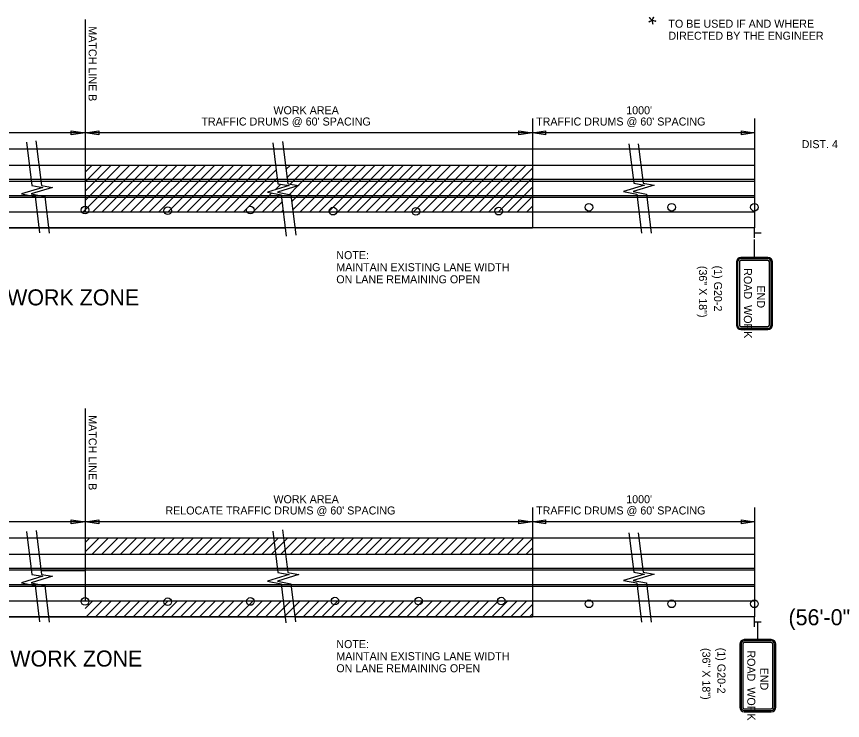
# Model space of a CAD drawing. Extents: x 1930579 to 1938445, y 596452 to 597630.
# Drawn here: x 1936946 to 1937565, y 596606 to 597134 of the extents above; entities that cross this region are included whole.
import ezdxf

# ---------------------------------------------------------------- set-up
doc = ezdxf.new("R2010")
doc.units = 0
for name, color, linetype in [('Default', 7, 'Continuous'), ('P_TC_Signs_Temporary', 7, 'Continuous'), ('R_Border', 7, 'Continuous')]:
    doc.layers.add(name, color=color, linetype=linetype)

msp = doc.modelspace()

# ---------------------------------------------------------------- linework, layer by layer
at = {"layer": 'Default'}
for p, q in [((1936997.05, 597131.34), (1936997.05, 596996.89)), ((1937332.4, 597057.24), (1937332.4, 596975.31)), ((1937498.74, 597057.24), (1937498.74, 596975.31)), ((1936997.05, 597046.45), (1936688.44, 597046.45)), ((1936986.74, 597044.9), (1936986.74, 597048)), ((1936986.74, 597048), (1936997.05, 597046.45)), ((1936997.05, 597046.45), (1936986.74, 597044.9)), ((1936997.05, 597046.45), (1937007.35, 597048)), ((1936997.05, 597047.93), (1936997.05, 596996.89)), ((1936997.05, 597047.92), (1936997.05, 596996.89)), ((1936997.05, 597047.92), (1936997.05, 596987.31)), ((1937332.4, 597046.45), (1936997.05, 597046.45)), ((1937007.35, 597044.9), (1936997.05, 597046.45)), ((1937007.35, 597048), (1937007.35, 597044.9)), ((1937322.09, 597044.9), (1937322.09, 597047.99)), ((1937322.09, 597047.99), (1937332.4, 597046.45)), ((1937332.4, 597046.45), (1937322.09, 597044.9)), ((1937332.4, 597046.45), (1937342.06, 597047.9)), ((1937342.06, 597045), (1937332.4, 597046.45)), ((1937498.74, 597046.45), (1937332.4, 597046.45)), ((1937342.06, 597047.9), (1937342.06, 597045)), ((1937489.08, 597045), (1937489.08, 597047.9)), ((1937489.08, 597047.9), (1937498.74, 597046.45)), ((1937498.74, 597046.45), (1937489.08, 597045)), ((1937498.74, 597034.31), (1936493.11, 597034.31)), ((1936493.11, 597022.31), (1937498.74, 597022.31)), ((1936995.74, 596987.31), (1937030.74, 597022.31)), ((1936997.05, 596995.68), (1937023.67, 597022.31)), ((1936997.05, 597002.75), (1937016.6, 597022.31)), ((1936997.05, 597009.83), (1937009.53, 597022.31)), ((1936997.05, 597016.9), (1937002.46, 597022.31)), ((1937002.81, 596987.31), (1937037.81, 597022.31)), ((1937009.89, 596987.31), (1937044.89, 597022.31)), ((1937016.96, 596987.31), (1937051.96, 597022.31)), ((1937024.03, 596987.31), (1937059.03, 597022.31)), ((1937031.1, 596987.31), (1937066.1, 597022.31)), ((1937038.17, 596987.31), (1937073.17, 597022.31)), ((1937045.24, 596987.31), (1937080.24, 597022.31)), ((1937052.31, 596987.31), (1937087.31, 597022.31)), ((1937059.38, 596987.31), (1937094.38, 597022.31)), ((1937066.45, 596987.31), (1937101.45, 597022.31)), ((1937073.53, 596987.31), (1937108.53, 597022.31)), ((1937080.6, 596987.31), (1937115.6, 597022.31)), ((1937087.67, 596987.31), (1937122.67, 597022.31)), ((1937094.74, 596987.31), (1937129.74, 597022.31)), ((1937101.81, 596987.31), (1937136.81, 597022.31)), ((1937147.64, 597018.99), (1937150.95, 597022.31)), ((1937148.42, 597012.71), (1937158.02, 597022.31)), ((1937150.83, 597008.04), (1937165.09, 597022.31)), ((1937152, 596995.07), (1937179.24, 597022.31)), ((1937152.76, 596988.76), (1937186.31, 597022.31)), ((1937156.84, 597006.98), (1937172.17, 597022.31)), ((1937158.38, 596987.31), (1937193.38, 597022.31)), ((1937165.45, 596987.31), (1937200.45, 597022.31)), ((1937172.52, 596987.31), (1937207.52, 597022.31)), ((1937179.59, 596987.31), (1937214.59, 597022.31)), ((1937186.66, 596987.31), (1937221.66, 597022.31)), ((1937193.73, 596987.31), (1937228.73, 597022.31)), ((1937200.8, 596987.31), (1937235.8, 597022.31)), ((1937207.88, 596987.31), (1937242.88, 597022.31)), ((1937214.95, 596987.31), (1937249.95, 597022.31)), ((1937222.02, 596987.31), (1937257.02, 597022.31)), ((1937229.09, 596987.31), (1937264.09, 597022.31)), ((1937236.16, 596987.31), (1937271.16, 597022.31)), ((1937243.23, 596987.31), (1937278.23, 597022.31)), ((1937250.3, 596987.31), (1937285.3, 597022.31)), ((1937257.37, 596987.31), (1937292.37, 597022.31)), ((1937264.44, 596987.31), (1937299.44, 597022.31)), ((1937271.52, 596987.31), (1937306.52, 597022.31)), ((1937278.59, 596987.31), (1937313.59, 597022.31)), ((1937285.66, 596987.31), (1937320.66, 597022.31)), ((1937292.73, 596987.31), (1937327.73, 597022.31)), ((1937108.88, 596987.31), (1937140.38, 597018.81)), ((1937299.8, 596987.31), (1937332.4, 597019.91)), ((1937498.74, 597011.52), (1936493.11, 597011.52)), ((1937498.74, 597010.14), (1936493.11, 597010.14)), ((1937115.95, 596987.31), (1937141.16, 597012.52)), ((1937139.45, 597003.73), (1937143.72, 597008.01)), ((1937306.87, 596987.31), (1937332.4, 597012.83)), ((1937150.22, 597000.37), (1937156.57, 597006.72)), ((1937313.94, 596987.31), (1937332.4, 597005.76)), ((1937498.74, 596999.34), (1936493.11, 596999.34)), ((1937498.74, 596998.03), (1936493.11, 596998.03)), ((1937123.02, 596987.31), (1937137.15, 597001.44)), ((1937130.09, 596987.31), (1937143.09, 597000.3)), ((1937321.01, 596987.31), (1937332.4, 596998.69)), ((1937137.17, 596987.31), (1937144.74, 596994.88)), ((1937328.08, 596987.31), (1937332.4, 596991.62)), ((1936493.11, 596987.31), (1937498.74, 596987.31)), ((1937144.24, 596987.31), (1937145.5, 596988.57)), ((1937498.74, 596975.31), (1936493.11, 596975.31)), ((1936757.75, 596975.31), (1937032.82, 596975.31)), ((1936970.07, 596975.31), (1936996.83, 596975.31)), ((1936996.83, 596975.31), (1937147.44, 596975.31)), ((1937155.09, 596975.31), (1937332.4, 596975.31)), ((1937498.63, 596975.29), (1937498.63, 596967.81)), ((1937498.74, 596971.57), (1937503.84, 596971.57)), ((1936997.05, 596839.97), (1936997.05, 596705.52)), ((1937332.4, 596765.87), (1937332.4, 596683.94)), ((1937498.74, 596765.87), (1937498.74, 596683.94)), ((1936997.05, 596755.08), (1936688.44, 596755.08)), ((1936986.74, 596753.53), (1936986.74, 596756.63)), ((1936986.74, 596756.63), (1936997.05, 596755.08)), ((1936997.05, 596755.08), (1936986.74, 596753.53)), ((1936997.05, 596755.08), (1937007.35, 596756.63)), ((1936997.05, 596756.56), (1936997.05, 596705.52)), ((1936997.05, 596756.55), (1936997.05, 596705.52)), ((1936997.05, 596756.55), (1936997.05, 596695.94)), ((1937332.4, 596755.08), (1936997.05, 596755.08)), ((1937007.35, 596753.53), (1936997.05, 596755.08)), ((1937007.35, 596756.63), (1937007.35, 596753.53)), ((1937322.09, 596753.53), (1937322.09, 596756.62)), ((1937322.09, 596756.62), (1937332.4, 596755.08)), ((1937332.4, 596755.08), (1937322.09, 596753.53)), ((1937332.4, 596755.08), (1937342.06, 596756.53)), ((1937498.74, 596755.08), (1937332.4, 596755.08)), ((1937342.06, 596753.63), (1937332.4, 596755.08)), ((1937342.06, 596756.53), (1937342.06, 596753.63)), ((1937489.08, 596753.63), (1937489.08, 596756.53)), ((1937489.08, 596756.53), (1937498.74, 596755.08)), ((1937498.74, 596755.08), (1937489.08, 596753.63)), ((1937498.74, 596742.94), (1936493.11, 596742.94)), ((1936997.05, 596732.6), (1937007.39, 596742.94)), ((1936997.05, 596739.67), (1937000.32, 596742.94)), ((1937002.46, 596730.94), (1937014.46, 596742.94)), ((1937009.53, 596730.94), (1937021.53, 596742.94)), ((1937016.6, 596730.94), (1937028.6, 596742.94)), ((1937023.67, 596730.94), (1937035.67, 596742.94)), ((1937030.74, 596730.94), (1937042.74, 596742.94)), ((1937037.81, 596730.94), (1937049.81, 596742.94)), ((1937044.89, 596730.94), (1937056.89, 596742.94)), ((1937051.96, 596730.94), (1937063.96, 596742.94)), ((1937059.03, 596730.94), (1937071.03, 596742.94)), ((1937066.1, 596730.94), (1937078.1, 596742.94)), ((1937073.17, 596730.94), (1937085.17, 596742.94)), ((1937080.24, 596730.94), (1937092.24, 596742.94)), ((1937087.31, 596730.94), (1937099.31, 596742.94)), ((1937094.38, 596730.94), (1937106.38, 596742.94)), ((1937101.45, 596730.94), (1937113.45, 596742.94)), ((1937108.53, 596730.94), (1937120.53, 596742.94)), ((1937115.6, 596730.94), (1937127.6, 596742.94)), ((1937122.67, 596730.94), (1937134.67, 596742.94)), ((1937129.74, 596730.94), (1937141.74, 596742.94)), ((1937136.81, 596730.94), (1937148.81, 596742.94)), ((1937143.88, 596730.94), (1937155.88, 596742.94)), ((1937150.95, 596730.94), (1937162.95, 596742.94)), ((1937158.02, 596730.94), (1937170.02, 596742.94)), ((1937165.09, 596730.94), (1937177.09, 596742.94)), ((1937172.17, 596730.94), (1937184.17, 596742.94)), ((1937179.24, 596730.94), (1937191.24, 596742.94)), ((1937186.31, 596730.94), (1937198.31, 596742.94)), ((1937193.38, 596730.94), (1937205.38, 596742.94)), ((1937200.45, 596730.94), (1937212.45, 596742.94)), ((1937207.52, 596730.94), (1937219.52, 596742.94)), ((1937214.59, 596730.94), (1937226.59, 596742.94)), ((1937221.66, 596730.94), (1937233.66, 596742.94)), ((1937228.73, 596730.94), (1937240.73, 596742.94)), ((1937235.8, 596730.94), (1937247.8, 596742.94)), ((1937242.88, 596730.94), (1937254.88, 596742.94)), ((1937249.95, 596730.94), (1937261.95, 596742.94)), ((1937257.02, 596730.94), (1937269.02, 596742.94)), ((1937264.09, 596730.94), (1937276.09, 596742.94)), ((1937271.16, 596730.94), (1937283.16, 596742.94)), ((1937278.23, 596730.94), (1937290.23, 596742.94)), ((1937285.3, 596730.94), (1937297.3, 596742.94)), ((1937292.37, 596730.94), (1937304.37, 596742.94)), ((1937299.44, 596730.94), (1937311.44, 596742.94)), ((1937306.52, 596730.94), (1937318.52, 596742.94)), ((1937313.59, 596730.94), (1937325.59, 596742.94)), ((1937320.66, 596730.94), (1937332.66, 596742.94)), ((1937327.73, 596730.94), (1937332.4, 596735.61)), ((1936493.11, 596730.94), (1937498.74, 596730.94)), ((1937498.74, 596720.15), (1936493.11, 596720.15)), ((1937498.74, 596718.77), (1936493.11, 596718.77)), ((1936964.36, 596718.71), (1936997.05, 596718.71)), ((1937498.74, 596707.98), (1936493.11, 596707.98)), ((1937498.74, 596706.66), (1936493.11, 596706.66)), ((1936493.11, 596695.94), (1937498.74, 596695.94)), ((1936997.05, 596690.17), (1937002.81, 596695.94)), ((1936997.89, 596683.94), (1937009.89, 596695.94)), ((1937004.96, 596683.94), (1937016.96, 596695.94)), ((1937012.03, 596683.94), (1937024.03, 596695.94)), ((1937019.1, 596683.94), (1937031.1, 596695.94)), ((1937026.17, 596683.94), (1937038.17, 596695.94)), ((1937033.24, 596683.94), (1937045.24, 596695.94)), ((1937040.31, 596683.94), (1937052.31, 596695.94)), ((1937047.38, 596683.94), (1937059.38, 596695.94)), ((1937054.45, 596683.94), (1937066.45, 596695.94)), ((1937061.53, 596683.94), (1937073.53, 596695.94)), ((1937068.6, 596683.94), (1937080.6, 596695.94)), ((1937075.67, 596683.94), (1937087.67, 596695.94)), ((1937082.74, 596683.94), (1937094.74, 596695.94)), ((1937089.81, 596683.94), (1937101.81, 596695.94)), ((1937096.88, 596683.94), (1937108.88, 596695.94)), ((1937103.95, 596683.94), (1937115.95, 596695.94)), ((1937111.02, 596683.94), (1937123.02, 596695.94)), ((1937118.09, 596683.94), (1937130.09, 596695.94)), ((1937125.17, 596683.94), (1937137.17, 596695.94)), ((1937132.24, 596683.94), (1937144.24, 596695.94)), ((1937139.31, 596683.94), (1937151.31, 596695.94)), ((1937146.38, 596683.94), (1937158.38, 596695.94)), ((1937153.45, 596683.94), (1937165.45, 596695.94)), ((1937160.52, 596683.94), (1937172.52, 596695.94)), ((1937167.59, 596683.94), (1937179.59, 596695.94)), ((1937174.66, 596683.94), (1937186.66, 596695.94)), ((1937181.73, 596683.94), (1937193.73, 596695.94)), ((1937188.8, 596683.94), (1937200.8, 596695.94)), ((1937195.88, 596683.94), (1937207.88, 596695.94)), ((1937202.95, 596683.94), (1937214.95, 596695.94)), ((1937210.02, 596683.94), (1937222.02, 596695.94)), ((1937217.09, 596683.94), (1937229.09, 596695.94)), ((1937224.16, 596683.94), (1937236.16, 596695.94)), ((1937231.23, 596683.94), (1937243.23, 596695.94)), ((1937238.3, 596683.94), (1937250.3, 596695.94)), ((1937245.37, 596683.94), (1937257.37, 596695.94)), ((1937252.44, 596683.94), (1937264.44, 596695.94)), ((1937259.52, 596683.94), (1937271.52, 596695.94)), ((1937266.59, 596683.94), (1937278.59, 596695.94)), ((1937273.66, 596683.94), (1937285.66, 596695.94)), ((1937280.73, 596683.94), (1937292.73, 596695.94)), ((1937287.8, 596683.94), (1937299.8, 596695.94)), ((1937294.87, 596683.94), (1937306.87, 596695.94)), ((1937301.94, 596683.94), (1937313.94, 596695.94)), ((1937309.01, 596683.94), (1937321.01, 596695.94)), ((1937316.08, 596683.94), (1937328.08, 596695.94)), ((1937323.16, 596683.94), (1937332.4, 596693.18)), ((1937330.23, 596683.94), (1937332.4, 596686.11)), ((1937498.74, 596683.94), (1936493.11, 596683.94)), ((1936757.75, 596683.94), (1937032.82, 596683.94)), ((1936970.07, 596683.94), (1936996.83, 596683.94)), ((1936996.83, 596683.94), (1937147.44, 596683.94)), ((1937155.09, 596683.94), (1937332.4, 596683.94)), ((1937498.63, 596683.92), (1937498.63, 596676.44)), ((1937498.74, 596680.2), (1937503.84, 596680.2))]:
    msp.add_line(p, q, dxfattribs=at)
for points in [[(1936953.13, 597039.54), (1936957.19, 597007.1), (1936965.44, 597005.64), (1936949.42, 597000.78), (1936959.62, 596998.84), (1936962.9, 596971.51)], [(1936960.31, 597040.43), (1936964.47, 597007.1), (1936972.73, 597005.64), (1936956.7, 597000.78), (1936966.9, 596998.84), (1936970.2, 596971.4)], [(1937137.85, 597039.06), (1937141.68, 597008.37), (1937149.94, 597006.91), (1937133.91, 597002.05), (1937144.11, 597000.11), (1937147.85, 596969.01)], [(1937145.02, 597039.96), (1937148.97, 597008.37), (1937157.22, 597006.91), (1937141.2, 597002.05), (1937151.39, 597000.11), (1937155.03, 596969.87)], [(1937404.64, 597038.31), (1937408.33, 597008.71), (1937416.4, 597007.29), (1937400.75, 597002.54), (1937410.71, 597000.64), (1937414.23, 596971.31)], [(1937411.75, 597038.31), (1937415.45, 597008.71), (1937423.51, 597007.29), (1937407.86, 597002.54), (1937417.82, 597000.64), (1937421.35, 596971.31)], [(1936960.36, 596748.67), (1936964.47, 596715.73), (1936972.73, 596714.27), (1936956.7, 596709.41), (1936966.9, 596707.47), (1936970.2, 596680.03)], [(1937137.8, 596748.1), (1937141.68, 596717), (1937149.94, 596715.54), (1937133.91, 596710.68), (1937144.11, 596708.74), (1937147.64, 596679.37)], [(1937144.97, 596749), (1937148.97, 596717), (1937157.22, 596715.54), (1937141.2, 596710.68), (1937151.39, 596708.74), (1937154.82, 596680.23)], [(1936953.18, 596747.77), (1936957.19, 596715.73), (1936965.44, 596714.27), (1936949.42, 596709.41), (1936959.62, 596707.47), (1936962.9, 596680.14)], [(1937404.64, 596746.94), (1937408.33, 596717.34), (1937416.4, 596715.92), (1937400.75, 596711.17), (1937410.71, 596709.27), (1937414.23, 596679.94)], [(1937411.75, 596746.94), (1937415.45, 596717.34), (1937423.51, 596715.92), (1937407.86, 596711.17), (1937417.82, 596709.27), (1937421.35, 596679.94)]]:
    msp.add_lwpolyline(points, dxfattribs=at)
for centre in [(1936997.05, 596988.6), (1937059.04, 596988.15), (1937121.03, 596988.57), (1937183.02, 596987.81), (1937245.02, 596987.66), (1937307.01, 596987.81), (1937374.75, 596990.76), (1937436.74, 596990.76), (1937498.74, 596990.76), (1937184.37, 596695.7), (1937247.04, 596695.68), (1937309.04, 596695.68), (1936997.05, 596695.46), (1937059.04, 596695.18), (1937121.03, 596695.41), (1937374.75, 596693.65), (1937436.74, 596693.65), (1937498.74, 596693.65)]:
    msp.add_circle(centre, 2.87, dxfattribs=at)
at = {"layer": 'P_TC_Signs_Temporary'}
for p, q in [((1937508.86, 596953.11), (1937488.61, 596953.11)), ((1937508.86, 596952.17), (1937488.61, 596952.17)), ((1937485.24, 596949.73), (1937485.24, 596902.48)), ((1937486.17, 596949.73), (1937486.17, 596902.48)), ((1937487.49, 596949.73), (1937487.49, 596902.48)), ((1937508.86, 596950.86), (1937488.61, 596950.86)), ((1937509.99, 596902.48), (1937509.99, 596949.73)), ((1937511.3, 596902.48), (1937511.3, 596949.73)), ((1937512.24, 596902.48), (1937512.24, 596949.73)), ((1937488.61, 596901.36), (1937508.86, 596901.36)), ((1937488.61, 596900.04), (1937508.86, 596900.04)), ((1937488.61, 596899.11), (1937508.86, 596899.11)), ((1937487.79, 596663.45), (1937487.79, 596616.2)), ((1937488.73, 596663.45), (1937488.73, 596616.2)), ((1937490.04, 596663.45), (1937490.04, 596616.2)), ((1937511.41, 596666.82), (1937491.16, 596666.82)), ((1937511.41, 596665.88), (1937491.16, 596665.88)), ((1937511.41, 596664.57), (1937491.16, 596664.57)), ((1937512.54, 596616.2), (1937512.54, 596663.45)), ((1937513.85, 596616.2), (1937513.85, 596663.45)), ((1937514.79, 596616.2), (1937514.79, 596663.45)), ((1937491.16, 596615.07), (1937511.41, 596615.07)), ((1937491.16, 596613.76), (1937511.41, 596613.76)), ((1937491.16, 596612.82), (1937511.41, 596612.82))]:
    msp.add_line(p, q, dxfattribs=at)
for centre, radius, start, end in [((1937488.61, 596949.73), 3.37, 90, 180), ((1937488.61, 596949.73), 2.44, 90, 180), ((1937508.86, 596949.73), 3.37, 360, 90), ((1937508.86, 596949.73), 2.44, 360, 90), ((1937488.61, 596949.73), 1.13, 90, 180), ((1937508.86, 596949.73), 1.13, 360, 90), ((1937488.61, 596902.48), 3.37, 180, 270), ((1937488.61, 596902.48), 2.44, 180, 270), ((1937488.61, 596902.48), 1.13, 180, 270), ((1937508.86, 596902.48), 2.44, 270, 360), ((1937508.86, 596902.48), 1.13, 270, 360), ((1937508.86, 596902.48), 3.38, 270, 360), ((1937491.16, 596663.45), 3.37, 90, 180), ((1937491.16, 596663.45), 2.44, 90, 180), ((1937491.16, 596663.45), 1.13, 90, 180), ((1937511.41, 596663.45), 3.37, 360, 90), ((1937511.41, 596663.45), 2.44, 360, 90), ((1937511.41, 596663.45), 1.13, 360, 90), ((1937491.16, 596616.2), 3.37, 180, 270), ((1937491.16, 596616.2), 2.44, 180, 270), ((1937491.16, 596616.2), 1.13, 180, 270), ((1937511.41, 596616.2), 2.44, 270, 360), ((1937511.41, 596616.2), 1.13, 270, 360), ((1937511.41, 596616.2), 3.38, 270, 360)]:
    msp.add_arc(centre, radius, start, end, dxfattribs=at)
at = {"layer": 'R_Border'}
for p, q in [((1937498.74, 596953.11), (1937498.74, 596966.48)), ((1937501.29, 596666.82), (1937501.29, 596680.2))]:
    msp.add_line(p, q, dxfattribs=at)

# ---------------------------------------------------------------- texts
at = {"layer": 'Default'}
for s, height, rotation, p in [('MATCH LINE B', 6, 270, (1936999.75, 597126.26)), ('WORK AREA', 6, 360, (1937138.26, 597060.38)), ("1000'", 6, 360, (1937402.67, 597060.38)), ("TRAFFIC DRUMS @ 60' SPACING", 6, 360, (1937084.29, 597051.95)), ("TRAFFIC DRUMS @ 60' SPACING", 6, 360, (1937335.13, 597051.95)), ('DIVERSION FOR LT. LANE WORK ZONE', 12, 360, (1936733.6, 596917.22)), ('MATCH LINE B', 6, 270, (1936999.75, 596834.89)), ('WORK AREA', 6, 360, (1937138.26, 596769.01)), ("1000'", 6, 360, (1937402.67, 596769.01)), ("RELOCATE TRAFFIC DRUMS @ 60' SPACING", 6, 360, (1937057.29, 596760.58)), ("TRAFFIC DRUMS @ 60' SPACING", 6, 360, (1937335.13, 596760.58)), ('DIVERSION FOR RT. LANE WORK ZONE', 12, 360, (1936733.32, 596646.67))]:
    msp.add_text(s, height=height, rotation=rotation, dxfattribs=at).set_placement(p)
msp.add_text('(56\'-0" CLEAR ROADWAY WIDTH ON BRIDGE DECK)', height=12, dxfattribs=at).set_placement((1937524.31, 596677.6))
at = {"layer": 'P_TC_Signs_Temporary'}
for s, p in [('ROAD  WORK', (1937490.86, 596945.07)), ('END', (1937500.61, 596932.14)), ('ROAD  WORK', (1937493.41, 596658.78)), ('END', (1937503.16, 596645.85))]:
    msp.add_text(s, height=6, rotation=270, dxfattribs=at).set_placement(p)
at = {"layer": 'R_Border'}
for s, height, rotation, p in [('*', 12, 45, (1937426.11, 597122.28)), ('TO BE USED IF AND WHERE', 6, 360, (1937434.29, 597125.22)), ('DIRECTED BY THE ENGINEER', 6, 360, (1937434.29, 597116.22)), ('DIST. 4', 6, 360, (1937534.18, 597034.99)), ('NOTE:', 6, 360, (1937185.39, 596951.85)), ('MAINTAIN EXISTING LANE WIDTH', 6, 360, (1937185.39, 596942.8)), ('(36" X 18")', 6, 270, (1937457.19, 596946.83)), ('(1) G20-2', 6, 270, (1937468.49, 596947.03)), ('ON LANE REMAINING OPEN', 6, 360, (1937185.39, 596933.75)), ('NOTE:', 6, 360, (1937185.39, 596660.48)), ('MAINTAIN EXISTING LANE WIDTH', 6, 360, (1937185.39, 596651.43)), ('(36" X 18")', 6, 270, (1937459.74, 596660.55)), ('(1) G20-2', 6, 270, (1937471.05, 596660.75)), ('ON LANE REMAINING OPEN', 6, 360, (1937185.39, 596642.38))]:
    msp.add_text(s, height=height, rotation=rotation, dxfattribs=at).set_placement(p)

doc.saveas('drawing.dxf')
